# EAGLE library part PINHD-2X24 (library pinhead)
PIN HEADER
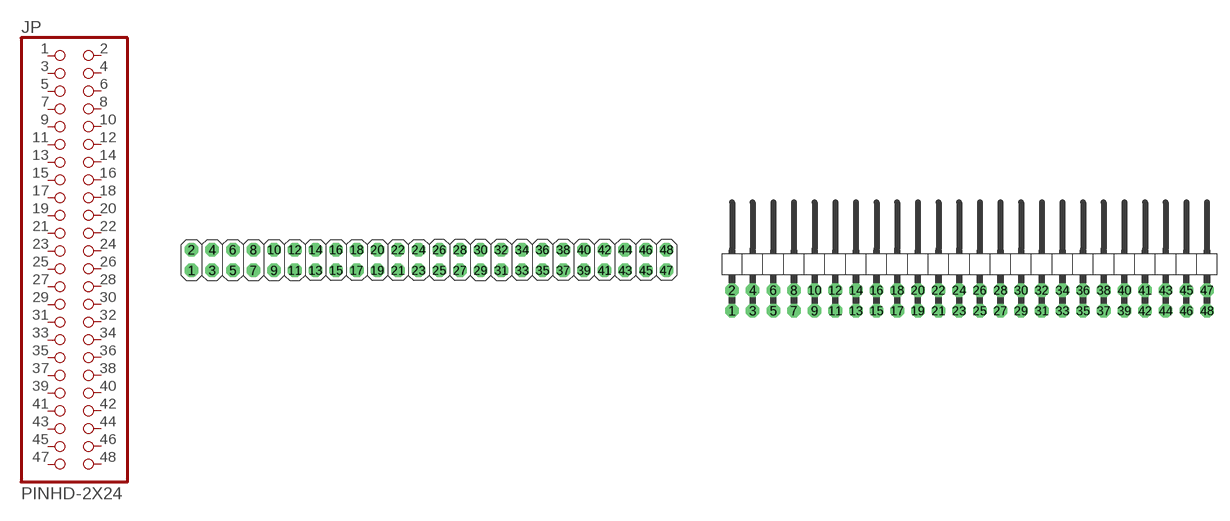
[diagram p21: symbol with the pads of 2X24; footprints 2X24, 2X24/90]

Designator prefix JP

## PINHD-2X24  [2X24]
1  1  pas
2  2  pas
3  3  pas
4  4  pas
5  5  pas
6  6  pas
7  7  pas
8  8  pas
9  9  pas
10  10  pas
11  11  pas
12  12  pas
13  13  pas
14  14  pas
15  15  pas
16  16  pas
17  17  pas
18  18  pas
19  19  pas
20  20  pas
21  21  pas
22  22  pas
23  23  pas
24  24  pas
25  25  pas
26  26  pas
27  27  pas
28  28  pas
29  29  pas
30  30  pas
31  31  pas
32  32  pas
33  33  pas
34  34  pas
35  35  pas
36  36  pas
37  37  pas
38  38  pas
39  39  pas
40  40  pas
41  41  pas
42  42  pas
43  43  pas
44  44  pas
45  45  pas
46  46  pas
47  47  pas
48  48  pas

## PINHD-2X24/90  [2X24/90]
Pads as for 2X24

## Footprint 2X24 (pad centres in mm)
PIN HEADER
drill 1.016 pad 1.67 octagon: 1 -27.94,-1.27; 2 -27.94,1.27; 3 -25.4,-1.27; 4 -25.4,1.27; 5 -22.86,-1.27; 6 -22.86,1.27; 7 -20.32,-1.27; 8 -20.32,1.27; 9 -17.78,-1.27; 10 -17.78,1.27; 11 -15.24,-1.27; 12 -15.24,1.27; 13 -12.7,-1.27; 14 -12.7,1.27; 15 -10.16,-1.27; 16 -10.16,1.27; 17 -7.62,-1.27; 18 -7.62,1.27; 19 -5.08,-1.27; 20 -5.08,1.27; 21 -2.54,-1.27; 22 -2.54,1.27; 23 0,-1.27; 24 0,1.27; 25 2.54,-1.27; 26 2.54,1.27; 27 5.08,-1.27; 28 5.08,1.27; 29 7.62,-1.27; 30 7.62,1.27; 31 10.16,-1.27; 32 10.16,1.27; 33 12.7,-1.27; 34 12.7,1.27; 35 15.24,-1.27; 36 15.24,1.27; 37 17.78,-1.27; 38 17.78,1.27; 39 20.32,-1.27; 40 20.32,1.27; 41 22.86,-1.27; 42 22.86,1.27; 43 25.4,-1.27; 44 25.4,1.27; 45 27.94,-1.27; 46 27.94,1.27; 47 30.48,-1.27; 48 30.48,1.27

## Footprint 2X24/90 (pad centres in mm)
PIN HEADER
drill 1.016 pad 1.67 octagon: 1 -29.21,-6.35; 2 -29.21,-3.81; 3 -26.67,-6.35; 4 -26.67,-3.81; 5 -24.13,-6.35; 6 -24.13,-3.81; 7 -21.59,-6.35; 8 -21.59,-3.81; 9 -19.05,-6.35; 10 -19.05,-3.81; 11 -16.51,-6.35; 12 -16.51,-3.81; 13 -13.97,-6.35; 14 -13.97,-3.81; 15 -11.43,-6.35; 16 -11.43,-3.81; 17 -8.89,-6.35; 18 -8.89,-3.81; 19 -6.35,-6.35; 20 -6.35,-3.81; 21 -3.81,-6.35; 22 -3.81,-3.81; 23 -1.27,-6.35; 24 -1.27,-3.81; 25 1.27,-6.35; 26 1.27,-3.81; 27 3.81,-6.35; 28 3.81,-3.81; 29 6.35,-6.35; 30 6.35,-3.81; 31 8.89,-6.35; 32 8.89,-3.81; 33 11.43,-6.35; 34 11.43,-3.81; 35 13.97,-6.35; 36 13.97,-3.81; 37 16.51,-6.35; 38 16.51,-3.81; 39 19.05,-6.35; 40 19.05,-3.81; 41 21.59,-3.81; 42 21.59,-6.35; 43 24.13,-3.81; 44 24.13,-6.35; 45 26.67,-3.81; 46 26.67,-6.35; 47 29.21,-3.81; 48 29.21,-6.35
